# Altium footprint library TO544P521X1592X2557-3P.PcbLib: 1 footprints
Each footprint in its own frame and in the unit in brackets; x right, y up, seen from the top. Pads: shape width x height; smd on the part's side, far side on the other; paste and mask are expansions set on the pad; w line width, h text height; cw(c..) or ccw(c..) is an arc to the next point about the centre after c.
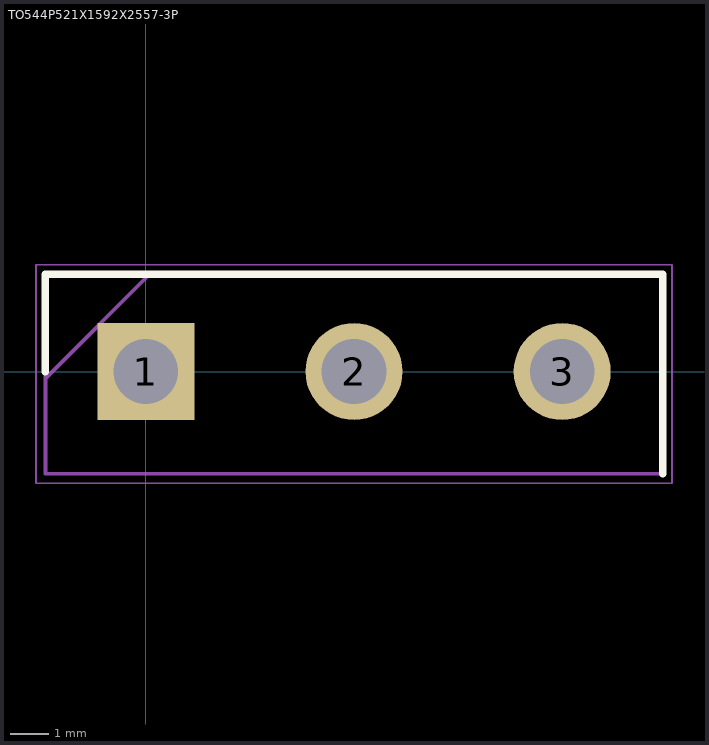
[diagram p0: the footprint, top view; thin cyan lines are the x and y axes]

## TO544P521X1592X2557-3P [mm]
pads (3):
  rect 2.535x2.535 / inner round 2.535 / far side rect 2.535x2.535 hole 1.69: 1(0,0)
  round 2.535 hole 1.69: 2(5.44,0) 3(10.88,0)
Top Overlay:
  lines w0.2: -2.625,0 -2.625,2.54 13.505,2.54 13.505,-2.67
Mechanical 15:
  lines w0.1: -2.625,-0.18 0.095,2.54 ; -2.625,-2.67 13.505,-2.67 13.505,2.54 -2.625,2.54 -2.625,-2.67
Mechanical 20:
  lines w0.05: -2.875,-2.92 13.755,-2.92 13.755,2.79 -2.875,2.79 -2.875,-2.92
